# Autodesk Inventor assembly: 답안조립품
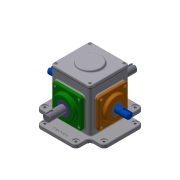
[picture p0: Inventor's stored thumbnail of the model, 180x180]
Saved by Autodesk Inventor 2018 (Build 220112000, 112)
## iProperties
Created: 2019-12
Part Number: 답안조립품
Material: 일반
Document SubType Name: Assembly
Designer: USER
Author: USER
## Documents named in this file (16)
- C:\Users\USER\Desktop\391204V1053\답안조립품.iam
- C:\Users\USER\Desktop\391204V1053\본체.ipt
- C:\Users\USER\Desktop\391204V1053\서브베벨기어.ipt
- C:\Users\USER\Desktop\391204V1053\서브축.ipt
- C:\Users\USER\Desktop\391204V1053\베어링 6203.ipt
- C:\Users\USER\Desktop\391204V1053\서브커버.ipt
- C:\Users\USER\Desktop\391204V1053\오일 실 17 32 8.ipt
- C:\Users\USER\Desktop\391204V1053\Ű 4x4.ipt
- C:\Users\USER\Desktop\391204V1053\볼트 M4.ipt
- C:\Users\USER\Desktop\391204V1053\메인베벨기어.ipt
- C:\Users\USER\Desktop\391204V1053\메인축.ipt
- C:\Users\USER\Desktop\391204V1053\베어링 6204.ipt
- C:\Users\USER\Desktop\391204V1053\메인커버.ipt
- C:\Users\USER\Desktop\391204V1053\오일 실 20 35 8.ipt
- C:\Users\USER\Desktop\391204V1053\개스킷.ipt
- C:\Users\USER\Desktop\391204V1053\상부커버.ipt
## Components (5 placed, 2 different names)
1. Ű 4x4:1
2. Ű 4x4:2
3. Ű 4x4:3
4. Ű 4x4:4
5. 개스킷:1
